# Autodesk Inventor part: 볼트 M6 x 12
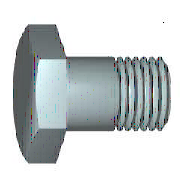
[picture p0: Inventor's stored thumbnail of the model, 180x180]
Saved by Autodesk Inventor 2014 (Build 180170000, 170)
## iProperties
IsCustomPart: 0
Created: 2012-02
Part Number: 볼트 M6 x 12
Material: 스테인리스강
Description: 6각 머리 나사. 제품 등급 C
Document SubType Name: Modeling
Standard: ISO 4018
Designer: mduedu
Standard Revision: Third edition 1999-08-15
Standards Organization: ISO
Language: ko-KR
Size Designation: M6 x 12
Categories: <MemberInstance><Categories><Category DisplayName="조임쇠" InternalName="e4da775c-781d-43d5-af7c-5136215cf5a6" Mnemonic="FSTN"><Category DisplayName="볼트" InternalN
Density: 8.08 g/cm^3
Appearance: 반광택
Author: mduedu
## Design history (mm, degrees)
node "WorkPlane1"
node "WorkPoint1"
node "MSC_A1"
node "MSC_PF1"
node "MSC_PT1"
body "Solid1"
node "스케치1"
sketch "스케치2"
  geometry: L1 (-5, 2.887)-(-5, -2.887); L2 (0, 5.773)-(-5, 2.887); L3 (5, 2.887)-(0, 5.773); L4 (5, -2.887)-(5, 2.887); L5 (0, -5.773)-(5, -2.887); L6 (-5, -2.887)-(0, -5.773); C1 r 5 at (0, 0); 1 further point
  constraints: 12 end point, 6 tangent, 2 parallel, 2 vertical, 1 centre point
  dimensions: "d1" = 10 diameter of C1 (= ParS); "d29" = 0 distance of point (0, 0) C1.centre; "d30" = 0 distance of C1.centre point (0, 0)
extrude "돌출1" new body sketch "스케치2" distance "d6" = 4 (= ParK); taper "d7" = 0 deg
revolve "회전1" stored, may be unused: angle "d14" = 360 deg
revolve "회전2" stored, may be unused: angle "d21" = 360 deg
chamfer "모따기1" distance "d22" = 0.5 (= 0.5 x PTC); stored, may be unused: second distance "d23" = 0.5 (= 0.5 x PTC), angle "d39" = 45 deg
fillet "모깎기1" dims "d24" = 0.25 (= r)
feature "스레드1" dims "d32" = 0, "b" = 10 (= NLG - 2 x PTC)
sketch "스케치3"
  geometry: L1 (5, 4)-(5.873, 4); L2 (5.873, 3.496)-(5, 4); L3 (5.873, 4)-(5.873, 3.496); L4 (0, -0.8)-(0, 4.8) reference; L5 (5.773, 0)-(5.773, 4) reference
  constraints: 6 end point, 1 horizontal, 1 vertical
  dimensions: "d25" = 0.1 distance between parallel lines of L5 L3; "d26" = 0 distance from line of L5.end L1; "d27" = 60 deg angle of L3 L2; "d28" = 5 distance from line of L4 L1.start (= 0.5 x ParS)
sketch "스케치4"
  geometry: L1 (0, -12)-(0, 0); L2 (-3, -12)-(0, -12); L3 (-3, 0)-(-3, -12); L4 (0, 0)-(-3, 0); L5 (0, -12)-(0, 0); L6 (-3.6, 0)-(0.6, 0) reference; L7 (0, -14.4)-(0, 2.4) reference
  constraints: 10 end point, 2 horizontal, 2 vertical
  dimensions: "d18" = 3 distance of L1.start L2.start (= 0.5 x NND); "d20" = 12 distance of L3.start L2.start (= NLG); "d33" = 0 distance between parallel lines of L7 L1; "d34" = 0 distance between parallel lines of L6 L4
other parameters: "NND" = 6 [user parameter; used in 2 equation terms], "NLG" = 12 [user parameter; used in 2 equation terms], "PTC" = 1 [user parameter; used in 3 equation terms], "ParK" = 4 [user parameter; used in 1 equation term], "ParS" = 10 [user parameter; used in 3 equation terms], "msp_es" = 5.77367 (= 0.577367 x ParS) [user parameter], "r" = 0.25 [user parameter; used in 1 equation term], "d2" = 15 (derived), "d4" = 17.32102 (derived), "d8" = 15 (derived), "d10" = 0 (derived), "d12" = 30 deg (derived), "d15" = 0 (derived), "d37" = 0, "d38" = 0, "d40" = 0, "d41" = 0, "d42" = 0, "THREADDIA" = 6 (= NND) [user parameter]
